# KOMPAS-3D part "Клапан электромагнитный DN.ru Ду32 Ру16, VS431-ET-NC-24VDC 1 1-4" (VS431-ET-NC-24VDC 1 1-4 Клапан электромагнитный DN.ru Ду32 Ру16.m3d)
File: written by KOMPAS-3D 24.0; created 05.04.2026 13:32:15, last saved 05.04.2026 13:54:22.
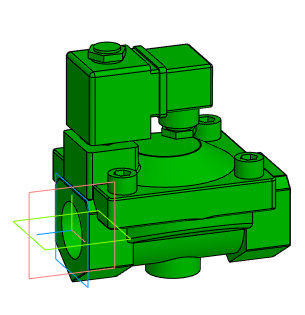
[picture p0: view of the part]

Document properties: Автор: artio; Полное имя файла: C:\Users\artio\OneDrive\Рабочий стол\Клапан электромагнитный DN.ru\VS431\VS431-ET-NC\VS431-ET-NC-24VDC\Ду32\VS431-ET-NC-24VDC 1 1-4 Клапан электромагнитный DN.ru Ду32 Ру16.m3d

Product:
- Body: Тело 1  | qty 1
    Масса: 3.709873
- Part/product: Клапан электромагнитный DN.ru Ду32 Ру16  | designation VS431-ET-NC-24VDC 1 1-4
    Масса: 1.701
    Раздел спецификации: Прочие изделия
    Примечание: D130-04743
    additional columns: ef56311e-7521-43dc-8291-0e6108b3d81d; artio; c; Шероховатость не задана; Да

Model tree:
1. Операция без истории:1

Expressions: VS431-ET-NC-24VDC 1 1-4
